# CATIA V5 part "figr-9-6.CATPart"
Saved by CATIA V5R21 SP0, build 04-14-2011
Part number: Part2
Bounding box of the stored display mesh (mm): x -75 to 75, y -75 to 96.278, z -26.878 to 0
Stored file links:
  D:\CATIA V5R21 E-RESOURCES\CATIA-V5R21\catia-v5r21-prt\c09-catia-v5r20-prt\c09-catia-v5r21-figr-9-6.CATPart
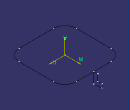
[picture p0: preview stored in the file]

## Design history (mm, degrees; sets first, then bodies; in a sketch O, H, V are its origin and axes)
Body1 (main body)
  Sketch1 on xy-plane, origin (0, 0, 0), H (1, 0, 0), V (0, 1, 0)
    point P1 (-75, 75)
    line L1 (-45, 75) -> (45, 75)
    line L2 (75, 45) -> (75, -45)
    line L3 (45, -75) -> (-45, -75)
    line L4 (-75, -45) -> (-75, 45)
    point P2 (75, 75)
    point P3 (75, -75)
    point P4 (-75, -75)
    axis line L5 (75, -75) -> (-75, 75)
    arc A1 centre (45, -45) radius 30 from (75, -45) to (45, -75) cw
    arc A2 centre (45, 45) radius 30 from (45, 75) to (75, 45) cw
    arc A3 centre (-45, 45) radius 30 from (-45, 75) to (-75, 45) ccw
    arc A4 centre (-45, -45) radius 30 from (-45, -75) to (-75, -45) cw
    distance P2 P3 = 150
    distance P3 P4 = 150
    radius A1 = 30
    radius A2 = 30
    radius A3 = 30
    radius A4 = 30
    horizontal: L1 H, L3 H
    vertical: L2 V, L4 V
    midpoint: O L5
    coincidence: L2 P3, L3 P3, L1 P2, L2 P2, L1 P1, L4 P1, L3 P4, L4 P4
    tangency: A1 L2, A1 L3, A2 L1, A2 L2, A3 L1, A3 L4, A4 L3, A4 L4
  Sketch2 on yz-plane, origin (0, 0, 0), H (0, 1, 0), V (0, 0, 1)
    point P1 (85, 0)
    line L1 (85, 0) -> (85, -16.8782)
    line L2 (85, -16.8782) -> (96.2781, -16.8782)
    line L3 (96.2781, -16.8782) -> (96.2781, -26.8782)
    line L4 (96.2781, -26.8782) -> (75, -26.8782)
    line L5 (75, -26.8782) -> (75, 0)
    point P6 (75, 0)
    line L6 (75, 0) -> (85, 0)
    reference projected point E1 (75, 0) from edge of Sketch1
    length L3 = 10
    length L6 = 10
    coincidence: P1 H, P6 H, P6 E1
    vertical: L1 V, L3 V, L5 V
    horizontal: L2 H, L4 H, L6 H
  Rib1: profile Sketch2, centre curve Sketch1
